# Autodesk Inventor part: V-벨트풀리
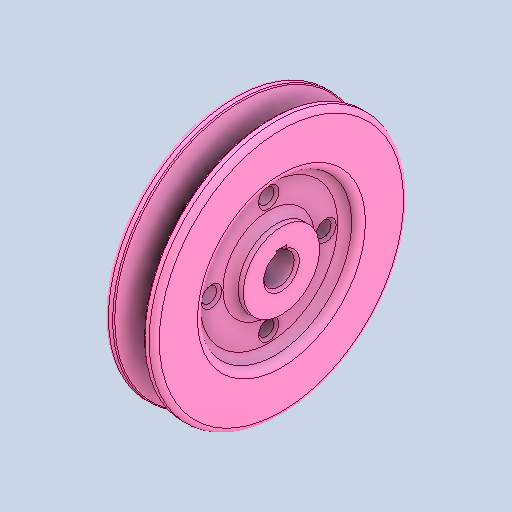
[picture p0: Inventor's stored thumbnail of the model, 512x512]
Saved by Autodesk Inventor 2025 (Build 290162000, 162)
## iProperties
Created: 2024-07
Part Number: V-벨트풀리
Material: 강철, 연강
Document SubType Name: Modeling
Designer: parkm
Density: 7.86 g/cm^3
Appearance: 기본값
Author: jhkim
Sending System: Autodesk Inventor 2025
Preprocessor: ST-DEVELOPER v20
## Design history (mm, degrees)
feature "솔리드1"
node "솔리드2"
